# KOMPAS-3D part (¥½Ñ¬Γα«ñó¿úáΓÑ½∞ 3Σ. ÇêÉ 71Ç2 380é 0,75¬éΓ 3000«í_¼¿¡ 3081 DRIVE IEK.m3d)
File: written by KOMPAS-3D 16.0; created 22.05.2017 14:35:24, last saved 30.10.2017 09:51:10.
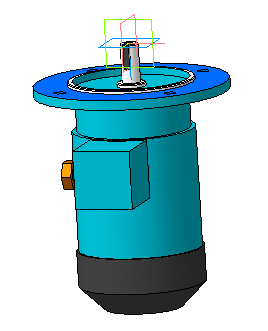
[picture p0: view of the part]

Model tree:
1. Операция без истории:1
2. Эскиз:1
3. Вырезать элемент выдавливания:1
     Расстояние 1 = 26

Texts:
  Body Specification ( left align )
  Body Specificaton ( centered )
